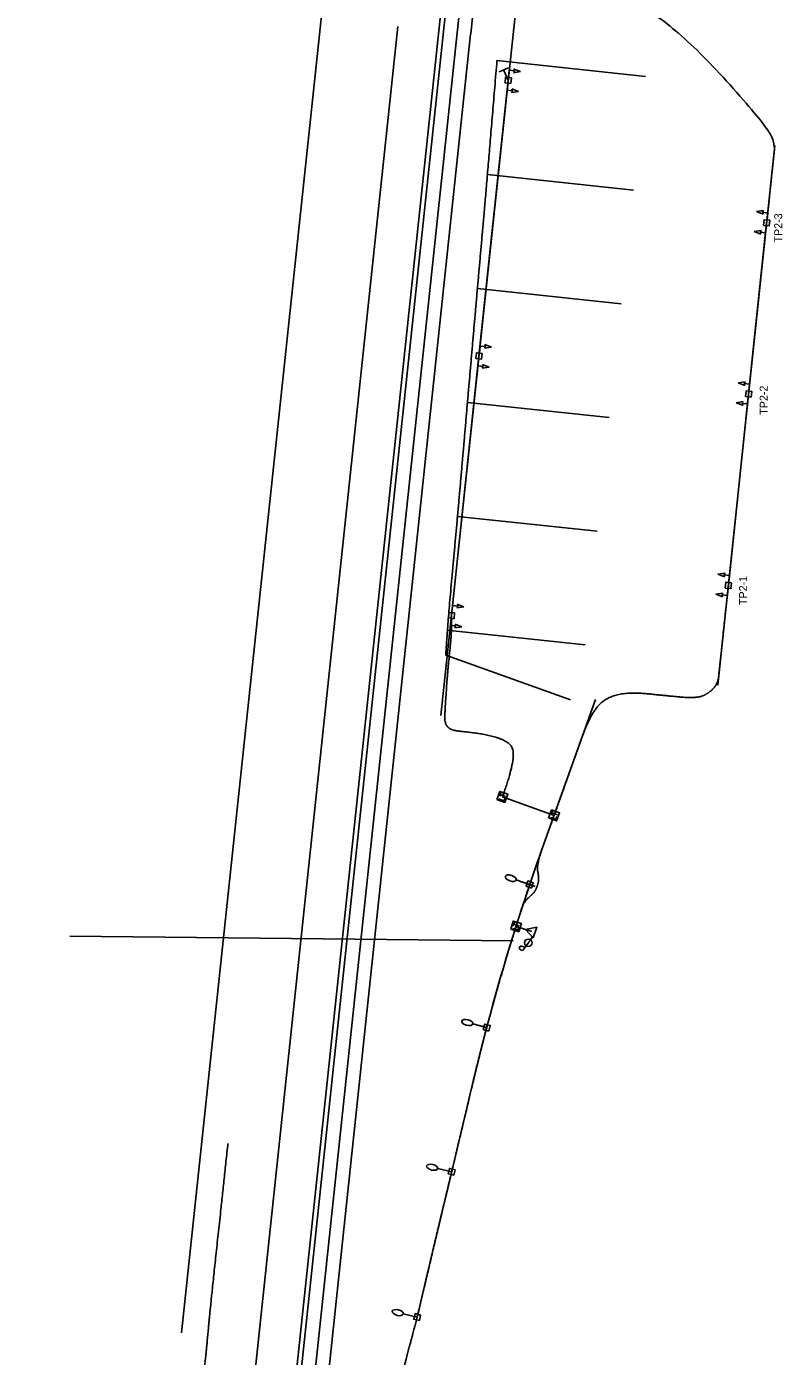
# Model space of a CAD drawing. Extents: x 172067 to 172728, y 250510 to 260293.
# Drawn here: x 172067 to 172728, y 254922 to 256085 of the extents above; entities that cross this region are included whole.
import ezdxf

# ---------------------------------------------------------------- set-up
doc = ezdxf.new("R2010")
doc.units = 0
for name, color, linetype in [('_CIVIL_CONSTRUCTION', 7, 'Continuous'), ('CM_Corridor_Final', 7, 'Continuous'), ('DR_P_Ditch', 7, 'Continuous'), ('DT_P_Graded_Shoulder', 7, 'Continuous'), ('DT_P_Tie', 7, 'Continuous'), ('MD_P_ACSC_T', 7, 'Continuous'), ('MD_P_GRADE_BREAK', 7, 'Continuous'), ('MD_P_Surface_Aggregate_Base', 7, 'Continuous'), ('MD_P_Surface_Asphalt_Concrete_Base', 7, 'Continuous'), ('MD_P_Surface_Asphalt_Concrete_Surface_Course', 7, 'Continuous'), ('MD_P_Surface_Ditch', 7, 'Continuous'), ('MD_P_Surface_Finished_Grade', 7, 'Continuous'), ('PV_P_Shoulder', 7, 'Continuous'), ('SC_Scratch1', 7, 'Continuous')]:
    doc.layers.add(name, color=color, linetype=linetype)

msp = doc.modelspace()

# ---------------------------------------------------------------- linework, layer by layer
at = {"layer": '_CIVIL_CONSTRUCTION'}
msp.add_line((172202.7, 254942.7), (172334.7, 256186.9), dxfattribs=at)
msp.add_open_spline([(172243.2, 255108.4), (172236.9, 255049.4), (172227.5, 254962), (172224.2, 254925.1), (172217.5, 254864.1), (172214.3, 254839), (172206.1, 254760.9), (172133.3, 254082.6), (172126.5, 254018.3), (172117.8, 253936.1), (172111.7, 253869.4), (172106.6, 253813.2), (172097.9, 253699.9), (172089, 253590.5), (172085, 253514.5), (172081.3, 253453.2), (172074.1, 253318.1), (172069.9, 253216.7), (172068, 253168.3), (172067.2, 253152.2)], degree=2, dxfattribs=at)
at = {"layer": 'CM_Corridor_Final'}
for p, q in [((172489.1, 256046.7), (172488.5, 256040.4)), ((172489.1, 256046.7), (172493.6, 256046.2)), ((172499.1, 256045.6), (172493, 256044.6)), ((172493.3, 256047.8), (172499.1, 256045.6)), ((172488, 256035.5), (172487.3, 256029.2)), ((172487.3, 256029.2), (172491.8, 256028.8)), ((172497.2, 256028.2), (172491.1, 256027.2)), ((172491.5, 256030.4), (172497.2, 256028.2)), ((172705.2, 255923.1), (172711.4, 255924.1)), ((172711, 255920.9), (172705.2, 255923.1)), ((172715.2, 255922.1), (172710.7, 255922.5)), ((172714.5, 255915.8), (172715.2, 255922.1)), ((172703.4, 255905.7), (172709.5, 255906.7)), ((172709.2, 255903.5), (172703.4, 255905.7)), ((172713.3, 255904.7), (172708.8, 255905.1)), ((172713.3, 255904.7), (172714, 255910.9)), ((172463.6, 255805.6), (172463, 255799.4)), ((172463.6, 255805.6), (172468.1, 255805.2)), ((172473.6, 255804.6), (172467.4, 255803.6)), ((172467.8, 255806.8), (172473.6, 255804.6)), ((172462.4, 255794.5), (172461.8, 255788.2)), ((172461.8, 255788.2), (172466.3, 255787.8)), ((172465.9, 255789.4), (172471.7, 255787.2)), ((172471.7, 255787.2), (172465.6, 255786.2)), ((172689.4, 255773.4), (172695.5, 255774.4)), ((172695.2, 255771.2), (172689.4, 255773.4)), ((172699.3, 255772.4), (172694.8, 255772.8)), ((172698.7, 255766.1), (172699.3, 255772.4)), ((172687.5, 255756), (172693.7, 255757)), ((172693.3, 255753.8), (172687.5, 255756)), ((172697.5, 255755), (172693, 255755.4)), ((172697.5, 255755), (172698.1, 255761.2)), ((172671.6, 255606), (172677.8, 255606.9)), ((172677.4, 255603.7), (172671.6, 255606)), ((172681.6, 255604.9), (172677.1, 255605.4)), ((172680.9, 255598.7), (172681.6, 255604.9)), ((172679.8, 255587.5), (172680.4, 255593.7)), ((172439.6, 255578.7), (172438.9, 255572.5)), ((172439.6, 255578.7), (172444.1, 255578.2)), ((172443.7, 255579.9), (172449.5, 255577.6)), ((172669.8, 255588.6), (172675.9, 255589.5)), ((172675.6, 255586.3), (172669.8, 255588.6)), ((172679.8, 255587.5), (172675.3, 255588)), ((172438.4, 255567.5), (172437.8, 255561.3)), ((172449.5, 255577.6), (172443.4, 255576.7)), ((172437.8, 255561.3), (172442.2, 255560.8)), ((172447.7, 255560.2), (172441.6, 255559.3)), ((172441.9, 255562.5), (172447.7, 255560.2)), ((172507, 255334.7), (172495.2, 255338.7)), ((172469.5, 255209.7), (172457.4, 255212.9)), ((172438.8, 255083.5), (172426.7, 255086.4)), ((172408.7, 254956.5), (172396.5, 254959.3))]:
    msp.add_line(p, q, dxfattribs=at)
for points in [[(172491, 256040.2), (172490.4, 256035.2), (172485.5, 256035.7), (172486, 256040.7)], [(172711.5, 255911.1), (172712, 255916.1), (172717, 255915.6), (172716.5, 255910.6)], [(172465.5, 255799.2), (172464.9, 255794.2), (172460, 255794.7), (172460.5, 255799.7)], [(172695.6, 255761.4), (172696.2, 255766.4), (172701.1, 255765.9), (172700.6, 255760.9)], [(172677.9, 255594), (172678.4, 255599), (172683.4, 255598.4), (172682.9, 255593.5)], [(172441.4, 255572.2), (172440.9, 255567.2), (172435.9, 255567.8), (172436.5, 255572.7)], [(172508.6, 255331.6), (172503.9, 255333.2), (172505.5, 255337.9), (172510.2, 255336.3)], [(172471.2, 255206.6), (172466.4, 255207.9), (172467.7, 255212.7), (172472.5, 255211.5)], [(172440.7, 255080.5), (172435.8, 255081.6), (172437, 255086.5), (172441.8, 255085.3)], [(172410.6, 254953.5), (172405.7, 254954.6), (172406.9, 254959.5), (172411.7, 254958.3)]]:
    msp.add_lwpolyline(points, close=True, dxfattribs=at)
for centre, start, end in [((172490.8, 256046.5), 319.4161, 28.4939), ((172489, 256029.1), 319.4161, 28.4939), ((172713.5, 255922.2), 139.4161, 208.4939), ((172711.7, 255904.8), 139.4161, 208.4939), ((172465.3, 255805.5), 319.4161, 28.4939), ((172463.4, 255788.1), 319.4161, 28.4939), ((172697.7, 255772.5), 139.4161, 208.4939), ((172695.8, 255755.1), 139.4161, 208.4939), ((172679.9, 255605.1), 139.4161, 208.4939), ((172441.3, 255578.5), 319.4161, 28.4939), ((172678.1, 255587.7), 139.4161, 208.4939), ((172439.4, 255561.1), 319.4161, 28.4939)]:
    msp.add_arc(centre, 2.84, start, end, dxfattribs=at)
for centre, major_axis in [((172490.5, 255340.3), (-4.74, 1.6)), ((172452.5, 255214.1), (-4.84, 1.27)), ((172421.8, 255087.5), (-4.86, 1.16)), ((172391.7, 254960.4), (-4.87, 1.14))]:
    msp.add_ellipse(centre, major_axis=major_axis, ratio=0.5, dxfattribs=at)
at = {"layer": 'DR_P_Ditch'}
for p, q in [((172462.7, 255796.9), (172488.2, 256038)), ((172698.4, 255763.7), (172714.2, 255913.4)), ((172438.7, 255570), (172462.7, 255796.9)), ((172680.7, 255596.2), (172698.4, 255763.7)), ((172483.2, 255411.3), (172528.4, 255395.1)), ((172508.9, 255293.6), (172495.1, 255298.1))]:
    msp.add_line(p, q, dxfattribs=at)
for points, degree in [([(172714.2, 255913.4), (172715.8, 255927.8), (172718.3, 255952.1), (172720.5, 255972.2), (172721.4, 255980.9), (172715.6, 255996.3), (172653.7, 256066), (172604.6, 256105.5), (172581.8, 256096.8), (172546, 256114.9), (172545, 256135.4), (172547, 256160.5), (172547.5, 256165.1), (172549.8, 256187), (172551.6, 256205.1), (172553.1, 256221.5)], 2), ([(172528.4, 255395.1), (172536, 255416.6), (172547.7, 255449.3), (172558.7, 255479.9), (172571, 255497), (172593.2, 255503.3), (172625.5, 255499.9), (172650.6, 255497.6), (172661.4, 255500.4), (172671.5, 255509.6), (172673, 255524.2), (172677, 255561.6), (172680.7, 255596.2)], 2), ([(172483.2, 255411.3), (172490.1, 255430.6), (172494, 255452.5), (172486.2, 255461), (172467.2, 255466.4), (172448.3, 255468.5), (172437.8, 255469.9), (172432.6, 255475.6), (172432.9, 255486), (172435.2, 255520.2), (172437.4, 255540.6), (172438.8, 255556.9), (172438.7, 255570)], 2), ([(172507, 255334.7), (172509.5, 255342.1), (172513.1, 255352.3), (172516.3, 255361.5), (172519.7, 255370.9), (172523, 255380.1), (172525.8, 255387.9), (172528.4, 255395.1)], 2), ([(172500.7, 255315.7), (172501.8, 255318.8), (172506.3, 255323.7), (172510.2, 255326.8), (172512.3, 255330.1), (172513.3, 255332.6), (172514.8, 255337.1), (172514.8, 255342.5), (172513.5, 255348.9), (172514.7, 255354.7), (172515.5, 255359.2), (172517.8, 255365.6)], 2), ([(172495.1, 255298.1), (172496.9, 255303.8), (172499.5, 255312.1), (172503.9, 255325.4), (172507, 255334.7)], 3), ([(172469.5, 255209.7), (172472.3, 255220.3), (172477, 255237.4), (172481.9, 255254.7), (172486.9, 255271.5), (172490.2, 255282.6), (172495.1, 255298.1)], 3), ([(172438.8, 255083.5), (172448.3, 255123.3), (172454.9, 255150.9), (172458.9, 255167.6), (172463.3, 255185.8), (172467.3, 255201.3), (172468.4, 255205.5), (172469.5, 255209.7)], 2), ([(172408.7, 254956.5), (172417.7, 254994.9), (172425.6, 255028.3), (172431.7, 255053.6), (172437, 255075.9), (172438.8, 255083.5)], 2), ([(172376.4, 254828.6), (172378.8, 254840), (172381.5, 254852.9), (172384.1, 254865), (172391.4, 254891.4), (172395.9, 254908), (172402.6, 254933.5), (172406.2, 254946.9), (172407.8, 254952.7), (172408.7, 254956.5)], 2)]:
    msp.add_open_spline(points, degree=degree, dxfattribs=at)
at = {"layer": 'DT_P_Graded_Shoulder'}
for p, q in [((172488.5, 256049), (172480.2, 256045.4)), ((172488.2, 256038), (172484.2, 256047.1))]:
    msp.add_line(p, q, dxfattribs=at)
at = {"layer": 'DT_P_Tie'}
msp.add_line((172492.5, 255285.5), (172105, 255289.6), dxfattribs=at)
at = {"layer": 'MD_P_ACSC_T'}
for p, q in [((172429.4, 255482.4), (172501.7, 256165.2)), ((172608.2, 256041.4), (172478.4, 256055.2)), ((172671.4, 255509), (172721.4, 255980.9)), ((172597.7, 255942), (172470.2, 255955.5)), ((172587.1, 255842.5), (172461.3, 255855.8)), ((172576.6, 255743.1), (172452.6, 255756.2)), ((172566.1, 255643.6), (172444, 255656.6)), ((172555.5, 255544.2), (172434.7, 255557)), ((172542.8, 255496.2), (172433.7, 255535.2)), ((172564.6, 255496.4), (172517.7, 255365.4)), ((172499, 255337.5), (172511.7, 255333.1)), ((172461.2, 255211.8), (172470, 255209.5)), ((172458.9, 255167.6), (172433.9, 255062.8))]:
    msp.add_line(p, q, dxfattribs=at)
msp.add_arc((174296.6, 254728.7), 1889.4, 160.3087, 166.5704, dxfattribs=at)
for points, degree in [([(172433.7, 255535.2), (172434.7, 255557), (172444, 255656.6), (172452.6, 255756.2), (172461.3, 255855.8), (172470.2, 255955.5), (172478.4, 256055.2)], 2), ([(172433.9, 255062.8), (172431.9, 255054.6), (172429.9, 255046.3), (172426, 255029.7), (172424, 255021.5), (172420.1, 255004.9), (172418.1, 254996.6), (172414.2, 254980.1), (172412.3, 254971.8), (172407.8, 254952.7)], 3)]:
    msp.add_open_spline(points, degree=degree, dxfattribs=at)
at = {"layer": 'MD_P_GRADE_BREAK'}
for p, q in [((172483.2, 255411.3), (172483.2, 255411.3)), ((172528.4, 255395.1), (172528.4, 255395.1)), ((172495.1, 255298.1), (172495.1, 255298.1))]:
    msp.add_line(p, q, dxfattribs=at)
for points in [[(172478.4, 255409), (172480.9, 255416.1), (172488, 255413.6), (172485.4, 255406.5)], [(172523.6, 255392.9), (172526.1, 255399.9), (172533.2, 255397.4), (172530.6, 255390.3)], [(172490.4, 255295.6), (172492.6, 255302.8), (172499.8, 255300.5), (172497.5, 255293.4)]]:
    msp.add_lwpolyline(points, close=True, dxfattribs=at)
for points in [[(172479.9, 255409.6), (172484.6, 255407.9), (172485.5, 255410.5)], [(172480.8, 255412), (172481.8, 255415)], [(172481.3, 255413.5), (172486, 255411.8)], [(172525.1, 255393.4), (172529.8, 255391.7), (172530.7, 255394.3)], [(172526, 255395.9), (172527, 255398.8)], [(172526.5, 255397.3), (172531.2, 255395.7)], [(172492.6, 255298.7), (172493.6, 255301.7)], [(172493.1, 255300.2), (172497.9, 255298.7)], [(172491.9, 255296.2), (172496.6, 255294.7), (172497.5, 255297.3)]]:
    msp.add_lwpolyline(points, dxfattribs=at)
at = {"layer": 'MD_P_Surface_Aggregate_Base'}
msp.add_line((172208.6, 254018.2), (172427.6, 256081.1), dxfattribs=at)
msp.add_arc((151025.9, 258352.5), 21521.9, 353.94188, 0.0466, dxfattribs=at)
at = {"layer": 'MD_P_Surface_Asphalt_Concrete_Base'}
msp.add_lwpolyline([(172510, 255288), (172513.2, 255297.3), (172503.4, 255295.5)], close=True, dxfattribs=at)
at = {"layer": 'MD_P_Surface_Asphalt_Concrete_Surface_Course'}
for p, q in [((172501.1, 255277), (172510, 255289.7)), ((172501.1, 255277), (172499.1, 255277.7)), ((172503, 255279.7), (172500.2, 255280.7))]:
    msp.add_line(p, q, dxfattribs=at)
msp.add_circle((172505.8, 255283.8), 3.25, dxfattribs=at)
msp.add_arc((172499.6, 255279.2), 1.59, 68.8285, 251.0751, dxfattribs=at)
at = {"layer": 'MD_P_Surface_Ditch'}
msp.add_line((172224.6, 254016.5), (172443.5, 256079.4), dxfattribs=at)
msp.add_arc((151025.9, 258352.5), 21537.9, 353.94188, 0.0466, dxfattribs=at)
at = {"layer": 'MD_P_Surface_Finished_Grade'}
for p, q in [((172212.6, 254017.8), (172431.6, 256080.7)), ((172236.5, 254015.2), (172455.4, 256078.2))]:
    msp.add_line(p, q, dxfattribs=at)
for radius in [21525.9, 21549.9]:
    msp.add_arc((151025.9, 258352.5), radius, 353.94188, 0.0466, dxfattribs=at)
at = {"layer": 'PV_P_Shoulder'}
for p, q in [((172528.4, 255395.1), (172483.2, 255411.3)), ((172508.9, 255293.6), (172495.1, 255298.1))]:
    msp.add_line(p, q, dxfattribs=at)
at = {"layer": 'SC_Scratch1'}
msp.add_line((172172.9, 254022), (172391.8, 256084.9), dxfattribs=at)
msp.add_line((172172.9, 254022), (172391.8, 256084.9), dxfattribs=at)
msp.add_line((172172.9, 254022), (172391.8, 256084.9), dxfattribs=at)
msp.add_line((172172.9, 254022), (172391.8, 256084.9), dxfattribs=at)

# ---------------------------------------------------------------- texts
at = {"layer": 'MD_P_ACSC_T'}
for s, p in [('TP2-3', (172727.8, 255896.1)), ('TP2-2', (172715.1, 255745.5)), ('TP2-1', (172697.1, 255579.1))]:
    msp.add_text(s, height=7, rotation=89.9803, dxfattribs=at).set_placement(p)

doc.saveas('drawing.dxf')
